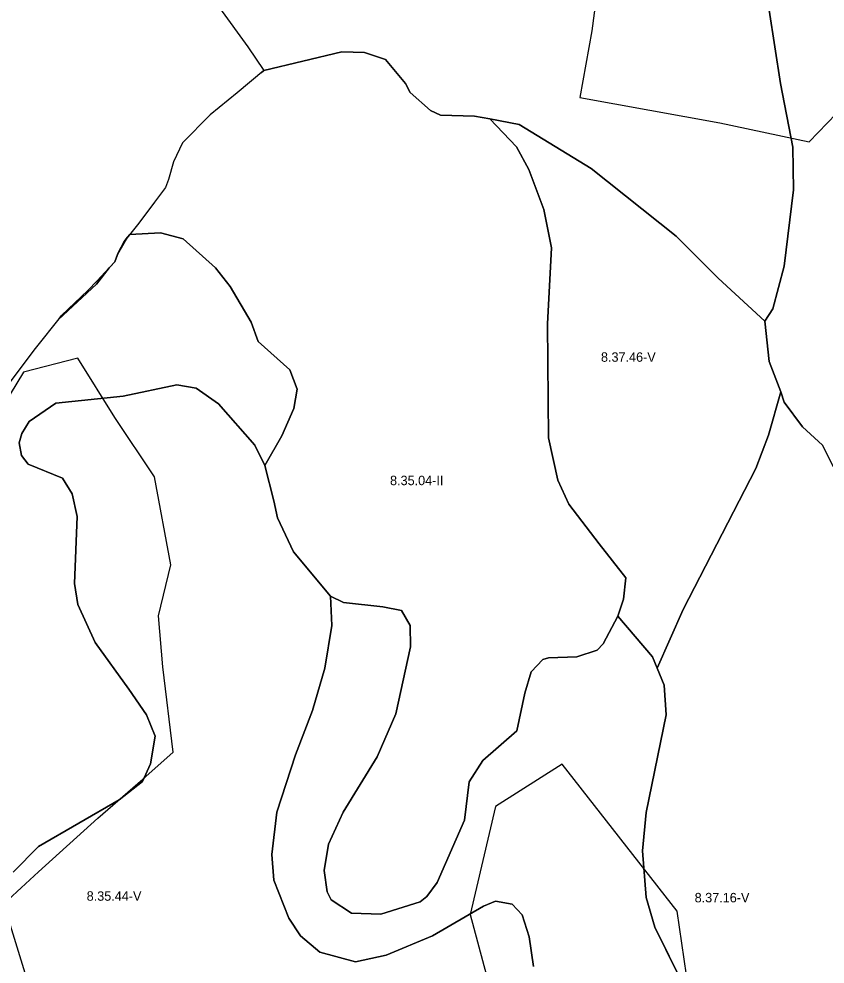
# Model space of a CAD drawing. Extents: x -547623 to -533936, y -1096714 to -1086523.
# Drawn here: x -540837 to -539983, y -1092678 to -1091678 of the extents above; entities that cross this region are included whole.
import ezdxf

# ---------------------------------------------------------------- set-up
doc = ezdxf.new("R2010")
doc.units = 0
for name, color, linetype in [('Vrstva 27', 7, 'Continuous'), ('Vrstva 28', 7, 'Continuous'), ('Vrstva 29', 7, 'Continuous')]:
    doc.layers.add(name, color=color, linetype=linetype)

msp = doc.modelspace()

# ---------------------------------------------------------------- linework, layer by layer
at = {"layer": 'Vrstva 28'}
for p, q in [((-540310, -1091813), (-540338, -1091783.5)), ((-540338, -1091783.5), (-540307, -1091789.5)), ((-540307, -1091789.5), (-540231, -1091836)), ((-540297, -1091837), (-540310, -1091813)), ((-540281, -1091879.5), (-540297, -1091837)), ((-540231, -1091836), (-540141, -1091907.5)), ((-540273, -1091920), (-540281, -1091879.5)), ((-540141, -1091907.5), (-540096.5, -1091952)), ((-540277, -1092000.5), (-540273, -1091920)), ((-540096.5, -1091952), (-540047, -1091997.5)), ((-540276, -1092121), (-540277, -1092000.5)), ((-540047, -1091997.5), (-540042.5, -1092040.5)), ((-540042.5, -1092040.5), (-540030, -1092072.5)), ((-540726.5, -1092077), (-540669.5, -1092065)), ((-540669.5, -1092065), (-540649, -1092068.5)), ((-540649, -1092068.5), (-540625.5, -1092085)), ((-540797.5, -1092084.5), (-540726.5, -1092077)), ((-540043, -1092118.5), (-540030, -1092072.5)), ((-540030, -1092072.5), (-540043, -1092118.5)), ((-540030, -1092072.5), (-540026.5, -1092083.5)), ((-540826, -1092104), (-540797.5, -1092084.5)), ((-540625.5, -1092085), (-540587, -1092129)), ((-540026.5, -1092083.5), (-540007, -1092109.5)), ((-540833.5, -1092116.5), (-540826, -1092104)), ((-540007, -1092109.5), (-539986, -1092129)), ((-540836.5, -1092126.5), (-540833.5, -1092116.5)), ((-540266, -1092166), (-540276, -1092121)), ((-540056.5, -1092153.5), (-540043, -1092118.5)), ((-540043, -1092118.5), (-540056.5, -1092153.5)), ((-540834, -1092140), (-540836.5, -1092126.5)), ((-540587, -1092129), (-540576.5, -1092150.5)), ((-539986, -1092129), (-539974.5, -1092151.5)), ((-540827, -1092149), (-540834, -1092140)), ((-540790.5, -1092164), (-540827, -1092149)), ((-540576.5, -1092150.5), (-540567, -1092188)), ((-540133.5, -1092303), (-540056.5, -1092153.5)), ((-540056.5, -1092153.5), (-540133.5, -1092303)), ((-540780.5, -1092180.5), (-540790.5, -1092164)), ((-540254.5, -1092191.5), (-540266, -1092166)), ((-540775, -1092204.5), (-540780.5, -1092180.5)), ((-540567, -1092188), (-540563, -1092206)), ((-540222.5, -1092233.5), (-540254.5, -1092191.5)), ((-540778, -1092275.5), (-540775, -1092204.5)), ((-540563, -1092206), (-540546, -1092242)), ((-540194, -1092269.5), (-540222.5, -1092233.5)), ((-540546, -1092242), (-540507, -1092289)), ((-540196.5, -1092292), (-540194, -1092269.5)), ((-540774.5, -1092297.5), (-540778, -1092275.5)), ((-540505.5, -1092320), (-540507, -1092289)), ((-540507, -1092289), (-540493, -1092295.5)), ((-540507, -1092289), (-540505.5, -1092320)), ((-540756, -1092338), (-540774.5, -1092297.5)), ((-540493, -1092295.5), (-540451.5, -1092300)), ((-540451.5, -1092300), (-540431.5, -1092304)), ((-540202.5, -1092310), (-540196.5, -1092292)), ((-540431.5, -1092304), (-540422.5, -1092320)), ((-540218, -1092339.5), (-540202.5, -1092310)), ((-540202.5, -1092310), (-540166, -1092353)), ((-540166, -1092353), (-540202.5, -1092310)), ((-540161, -1092365), (-540133.5, -1092303)), ((-540133.5, -1092303), (-540161, -1092365)), ((-540513, -1092365), (-540505.5, -1092320)), ((-540505.5, -1092320), (-540513, -1092365)), ((-540422.5, -1092320), (-540422, -1092342.5)), ((-540720.5, -1092387.5), (-540756, -1092338)), ((-540224.5, -1092346), (-540218, -1092339.5)), ((-540422, -1092342.5), (-540437.5, -1092413.5)), ((-540246, -1092353), (-540224.5, -1092346)), ((-540294.5, -1092369), (-540282, -1092356)), ((-540282, -1092356), (-540276, -1092354)), ((-540276, -1092354), (-540246, -1092353)), ((-540166, -1092353), (-540161, -1092365)), ((-540161, -1092365), (-540166, -1092353)), ((-540526, -1092410), (-540513, -1092365)), ((-540513, -1092365), (-540526, -1092410)), ((-540301, -1092391.5), (-540294.5, -1092369)), ((-540161, -1092365), (-540153.5, -1092383)), ((-540153.5, -1092383), (-540161, -1092365)), ((-540701.5, -1092414.5), (-540720.5, -1092387.5)), ((-540153.5, -1092383), (-540151.5, -1092414.5)), ((-540151.5, -1092414.5), (-540153.5, -1092383)), ((-540309.5, -1092431.5), (-540301, -1092391.5)), ((-540544, -1092457), (-540526, -1092410)), ((-540526, -1092410), (-540544, -1092457)), ((-540692.5, -1092437), (-540701.5, -1092414.5)), ((-540437.5, -1092413.5), (-540457.5, -1092459)), ((-540151.5, -1092414.5), (-540172.5, -1092518)), ((-540172.5, -1092518), (-540151.5, -1092414.5)), ((-540697.5, -1092466.5), (-540692.5, -1092437)), ((-540345.5, -1092463), (-540309.5, -1092431.5)), ((-540563.5, -1092517.5), (-540544, -1092457)), ((-540544, -1092457), (-540563.5, -1092517.5)), ((-540457.5, -1092459), (-540493.5, -1092517.5)), ((-540706, -1092485), (-540697.5, -1092466.5)), ((-540360, -1092485.5), (-540345.5, -1092463)), ((-540730.5, -1092504.5), (-540706, -1092485)), ((-540365, -1092526), (-540360, -1092485.5)), ((-540816, -1092554), (-540730.5, -1092504.5)), ((-540569, -1092562.5), (-540563.5, -1092517.5)), ((-540563.5, -1092517.5), (-540569, -1092562.5)), ((-540493.5, -1092517.5), (-540509, -1092551.5)), ((-540172.5, -1092518), (-540176.5, -1092558.5)), ((-540176.5, -1092558.5), (-540172.5, -1092518)), ((-540394, -1092592), (-540365, -1092526)), ((-540843, -1092581), (-540816, -1092554)), ((-540509, -1092551.5), (-540513.5, -1092579.5)), ((-540176.5, -1092558.5), (-540172.5, -1092608)), ((-540172.5, -1092608), (-540176.5, -1092558.5)), ((-540567, -1092589.5), (-540569, -1092562.5)), ((-540569, -1092562.5), (-540567, -1092589.5)), ((-540513.5, -1092579.5), (-540510.5, -1092602)), ((-540551, -1092630), (-540567, -1092589.5)), ((-540567, -1092589.5), (-540551, -1092630)), ((-540405, -1092607), (-540394, -1092592)), ((-540510.5, -1092602), (-540506, -1092610.5)), ((-540506, -1092610.5), (-540484.5, -1092624.5)), ((-540412, -1092612.5), (-540405, -1092607)), ((-540172.5, -1092608), (-540163.5, -1092639.5)), ((-540163.5, -1092639.5), (-540172.5, -1092608)), ((-540453.5, -1092625.5), (-540412, -1092612.5)), ((-540345, -1092617), (-540399, -1092648.5)), ((-540399, -1092648.5), (-540345, -1092617)), ((-540332, -1092612), (-540345, -1092617)), ((-540345, -1092617), (-540332, -1092612)), ((-540314.5, -1092615), (-540332, -1092612)), ((-540332, -1092612), (-540314.5, -1092615)), ((-540304, -1092626.5), (-540314.5, -1092615)), ((-540314.5, -1092615), (-540304, -1092626.5)), ((-540538.5, -1092648.5), (-540551, -1092630)), ((-540551, -1092630), (-540538.5, -1092648.5)), ((-540484.5, -1092624.5), (-540453.5, -1092625.5)), ((-540296.5, -1092649.5), (-540304, -1092626.5)), ((-540304, -1092626.5), (-540296.5, -1092649.5)), ((-540163.5, -1092639.5), (-540128, -1092711)), ((-540128, -1092711), (-540163.5, -1092639.5)), ((-540518, -1092666), (-540538.5, -1092648.5)), ((-540538.5, -1092648.5), (-540518, -1092666)), ((-540399, -1092648.5), (-540448, -1092669)), ((-540448, -1092669), (-540399, -1092648.5)), ((-540292, -1092681), (-540296.5, -1092649.5)), ((-540296.5, -1092649.5), (-540292, -1092681)), ((-540480.5, -1092676), (-540518, -1092666)), ((-540518, -1092666), (-540480.5, -1092676)), ((-540448, -1092669), (-540480.5, -1092676)), ((-540480.5, -1092676), (-540448, -1092669))]:
    msp.add_line(p, q, dxfattribs=at)
for points in [[(-540048.5, -1091629), (-540030.5, -1091746), (-540017.5, -1091813.5), (-540016.5, -1091858.5), (-540026.5, -1091939.5), (-540038.5, -1091984.5), (-540047, -1091997.5), (-540096.5, -1091952), (-540141, -1091907.5), (-540231, -1091836), (-540307, -1091789.5), (-540338, -1091783.5), (-540354.5, -1091780.5), (-540390.5, -1091779.5), (-540401, -1091774.5), (-540422.5, -1091755.5), (-540427.5, -1091746), (-540448.5, -1091720.5), (-540471, -1091713), (-540495, -1091712.5), (-540577.5, -1091732.3)], [(-539974.5, -1092151.5), (-539986, -1092129), (-540007, -1092109.5), (-540026.5, -1092083.5), (-540030, -1092072.5), (-540042.5, -1092040.5), (-540047, -1091997.5), (-540038.5, -1091984.5), (-540026.5, -1091939.5), (-540016.5, -1091858.5), (-540017.5, -1091813.5), (-540030.5, -1091746), (-540048.5, -1091629)], [(-540624.5, -1091665.9), (-540594.5, -1091707), (-540577.5, -1091732.3), (-540605.7, -1091755.9), (-540634.2, -1091779.2), (-540663.6, -1091808.7), (-540673.2, -1091828.9), (-540678.4, -1091847.7), (-540681.4, -1091856.2), (-540693.1, -1091871.6), (-540709.8, -1091893.9), (-540725.4, -1091913.4), (-540731.8, -1091925.2), (-540735.2, -1091934.7), (-540753.8, -1091954.9), (-540763.7, -1091965.3), (-540791.7, -1091991.7), (-540820.9, -1092028.4), (-540846, -1092061.8)], [(-540577.5, -1091732.3), (-540495, -1091712.5), (-540471, -1091713), (-540448.5, -1091720.5), (-540427.5, -1091746), (-540422.5, -1091755.5), (-540401, -1091774.5), (-540390.5, -1091779.5), (-540354.5, -1091780.5), (-540338, -1091783.5), (-540310, -1091813), (-540297, -1091837), (-540281, -1091879.5), (-540273, -1091920), (-540277, -1092000.5), (-540276, -1092121), (-540266, -1092166), (-540254.5, -1092191.5), (-540222.5, -1092233.5), (-540194, -1092269.5), (-540196.5, -1092292), (-540202.5, -1092310), (-540218, -1092339.5), (-540224.5, -1092346), (-540246, -1092353), (-540276, -1092354), (-540282, -1092356), (-540294.5, -1092369), (-540301, -1092391.5), (-540309.5, -1092431.5), (-540345.5, -1092463), (-540360, -1092485.5), (-540365, -1092526), (-540394, -1092592), (-540405, -1092607), (-540412, -1092612.5), (-540453.5, -1092625.5), (-540484.5, -1092624.5), (-540506, -1092610.5), (-540510.5, -1092602), (-540513.5, -1092579.5), (-540509, -1092551.5), (-540493.5, -1092517.5), (-540457.5, -1092459), (-540437.5, -1092413.5), (-540422, -1092342.5), (-540422.5, -1092320), (-540431.5, -1092304), (-540451.5, -1092300), (-540493, -1092295.5), (-540507, -1092289), (-540546, -1092242), (-540563, -1092206), (-540567, -1092188), (-540576.5, -1092150.5), (-540558.5, -1092119), (-540545.5, -1092090), (-540542, -1092069.5), (-540550, -1092049), (-540583.5, -1092019), (-540591, -1091998.5), (-540613, -1091961), (-540628.5, -1091941), (-540663, -1091910.5), (-540687, -1091904), (-540719.4, -1091906)], [(-540580.3, -1091734.7), (-540577.5, -1091732.3), (-540577.5, -1091732.3)], [(-540047, -1091997.5), (-540096.5, -1091952), (-540141, -1091907.5), (-540231, -1091836), (-540307, -1091789.5), (-540338, -1091783.5), (-540310, -1091813), (-540297, -1091837), (-540281, -1091879.5), (-540273, -1091920), (-540277, -1092000.5), (-540276, -1092121), (-540266, -1092166), (-540254.5, -1092191.5), (-540222.5, -1092233.5), (-540194, -1092269.5), (-540196.5, -1092292), (-540202.5, -1092310), (-540166, -1092353), (-540161, -1092365), (-540133.5, -1092303), (-540056.5, -1092153.5), (-540043, -1092118.5), (-540030, -1092072.5), (-540042.5, -1092040.5), (-540047, -1091997.5)], [(-540719.4, -1091906), (-540687, -1091904), (-540663, -1091910.5), (-540628.5, -1091941), (-540613, -1091961), (-540591, -1091998.5), (-540583.5, -1092019), (-540550, -1092049), (-540542, -1092069.5), (-540545.5, -1092090), (-540558.5, -1092119), (-540576.5, -1092150.5), (-540587, -1092129), (-540625.5, -1092085), (-540649, -1092068.5), (-540669.5, -1092065), (-540726.5, -1092077), (-540797.5, -1092084.5), (-540826, -1092104), (-540833.5, -1092116.5), (-540836.5, -1092126.5), (-540834, -1092140), (-540827, -1092149), (-540790.5, -1092164), (-540780.5, -1092180.5), (-540775, -1092204.5), (-540778, -1092275.5), (-540774.5, -1092297.5), (-540756, -1092338), (-540720.5, -1092387.5), (-540701.5, -1092414.5), (-540692.5, -1092437), (-540697.5, -1092466.5), (-540706, -1092485), (-540730.5, -1092504.5), (-540816, -1092554), (-540843, -1092581)], [(-540732.5, -1091927.1), (-540721.6, -1091908.6)], [(-540721.6, -1091908.6), (-540732.5, -1091927.1)], [(-540732.5, -1091927.1), (-540731.8, -1091925.2), (-540725.4, -1091913.4), (-540721.6, -1091908.6)], [(-540721.6, -1091908.6), (-540719.4, -1091906)], [(-540721.6, -1091908.6), (-540721.6, -1091908.6)], [(-540719.4, -1091906), (-540719.4, -1091906)], [(-540741.3, -1091941.3), (-540735.2, -1091934.7), (-540732.5, -1091927.1)], [(-540795, -1091995.8), (-540754.5, -1091958.5), (-540741.3, -1091941.3), (-540741.3, -1091941.3)], [(-540741.3, -1091941.3), (-540741.3, -1091941.3), (-540754.5, -1091958.5), (-540795, -1091995.8)], [(-540795, -1091995.8), (-540791.7, -1091991.7), (-540763.7, -1091965.3), (-540753.8, -1091954.9), (-540741.3, -1091941.3)], [(-540292, -1092681), (-540296.5, -1092649.5), (-540304, -1092626.5), (-540314.5, -1092615), (-540332, -1092612), (-540345, -1092617), (-540399, -1092648.5), (-540448, -1092669), (-540480.5, -1092676), (-540518, -1092666), (-540538.5, -1092648.5), (-540551, -1092630), (-540567, -1092589.5), (-540569, -1092562.5), (-540563.5, -1092517.5), (-540544, -1092457), (-540526, -1092410), (-540513, -1092365), (-540505.5, -1092320), (-540507, -1092289), (-540546, -1092242), (-540563, -1092206), (-540567, -1092188), (-540576.5, -1092150.5), (-540587, -1092129), (-540625.5, -1092085), (-540649, -1092068.5), (-540669.5, -1092065), (-540726.5, -1092077), (-540797.5, -1092084.5), (-540826, -1092104), (-540833.5, -1092116.5), (-540836.5, -1092126.5), (-540834, -1092140), (-540827, -1092149), (-540790.5, -1092164), (-540780.5, -1092180.5), (-540775, -1092204.5), (-540778, -1092275.5), (-540774.5, -1092297.5), (-540756, -1092338), (-540720.5, -1092387.5), (-540701.5, -1092414.5), (-540692.5, -1092437), (-540697.5, -1092466.5), (-540706, -1092485), (-540730.5, -1092504.5), (-540816, -1092554), (-540843, -1092581)], [(-539974.5, -1092151.5), (-539986, -1092129), (-540007, -1092109.5), (-540026.5, -1092083.5), (-540030, -1092072.5), (-540043, -1092118.5), (-540056.5, -1092153.5), (-540133.5, -1092303), (-540161, -1092365), (-540153.5, -1092383), (-540151.5, -1092414.5), (-540172.5, -1092518), (-540176.5, -1092558.5), (-540172.5, -1092608), (-540163.5, -1092639.5), (-540128, -1092711)], [(-540128, -1092711), (-540163.5, -1092639.5), (-540172.5, -1092608), (-540176.5, -1092558.5), (-540172.5, -1092518), (-540151.5, -1092414.5), (-540153.5, -1092383), (-540161, -1092365), (-540166, -1092353), (-540202.5, -1092310), (-540218, -1092339.5), (-540224.5, -1092346), (-540246, -1092353), (-540276, -1092354), (-540282, -1092356), (-540294.5, -1092369), (-540301, -1092391.5), (-540309.5, -1092431.5), (-540345.5, -1092463), (-540360, -1092485.5), (-540365, -1092526), (-540394, -1092592), (-540405, -1092607), (-540412, -1092612.5), (-540453.5, -1092625.5), (-540484.5, -1092624.5), (-540506, -1092610.5), (-540510.5, -1092602), (-540513.5, -1092579.5), (-540509, -1092551.5), (-540493.5, -1092517.5), (-540457.5, -1092459), (-540437.5, -1092413.5), (-540422, -1092342.5), (-540422.5, -1092320), (-540431.5, -1092304), (-540451.5, -1092300), (-540493, -1092295.5), (-540507, -1092289), (-540505.5, -1092320), (-540513, -1092365), (-540526, -1092410), (-540544, -1092457), (-540563.5, -1092517.5), (-540569, -1092562.5), (-540567, -1092589.5), (-540551, -1092630), (-540538.5, -1092648.5), (-540518, -1092666), (-540480.5, -1092676), (-540448, -1092669), (-540399, -1092648.5), (-540345, -1092617), (-540332, -1092612), (-540314.5, -1092615), (-540304, -1092626.5), (-540296.5, -1092649.5), (-540292, -1092681)]]:
    msp.add_lwpolyline(points, dxfattribs=at)
at = {"layer": 'Vrstva 29'}
for points in [[(-540221.2, -1091623.2), (-540230.3, -1091690.3), (-540242.9, -1091760.6), (-540094.8, -1091787.5), (-540000, -1091807.8), (-539962.1, -1091768.2), (-539937.2, -1091732.2), (-539911.5, -1091674.3)], [(-540784.8, -1092834.8), (-540852.7, -1092614.8), (-540816, -1092580.9), (-540753.2, -1092524), (-540705.7, -1092482.8), (-540673.6, -1092454.1), (-540684.5, -1092363.8), (-540689.1, -1092309.7), (-540675.8, -1092255.6), (-540693.2, -1092162.5), (-540735.3, -1092099.8), (-540774.5, -1092036.9), (-540831.9, -1092051.7), (-540931.1, -1092214.7)], [(-540122.6, -1092741), (-540139.9, -1092622.3), (-540261.6, -1092466.7), (-540332, -1092511.5), (-540358.9, -1092626.1), (-540342.2, -1092689.2)]]:
    msp.add_lwpolyline(points, dxfattribs=at)

# ---------------------------------------------------------------- texts
at = {"layer": 'Vrstva 27'}
for s, p in [('8.37.46-V', (-540220.5, -1092040.6)), ('8.35.04-II', (-540443.8, -1092171.3)), ('8.35.44-V', (-540765, -1092611.4)), ('8.37.16-V', (-540121.3, -1092613.1))]:
    msp.add_text(s, height=10, dxfattribs=at).set_placement(p)

doc.saveas('drawing.dxf')
